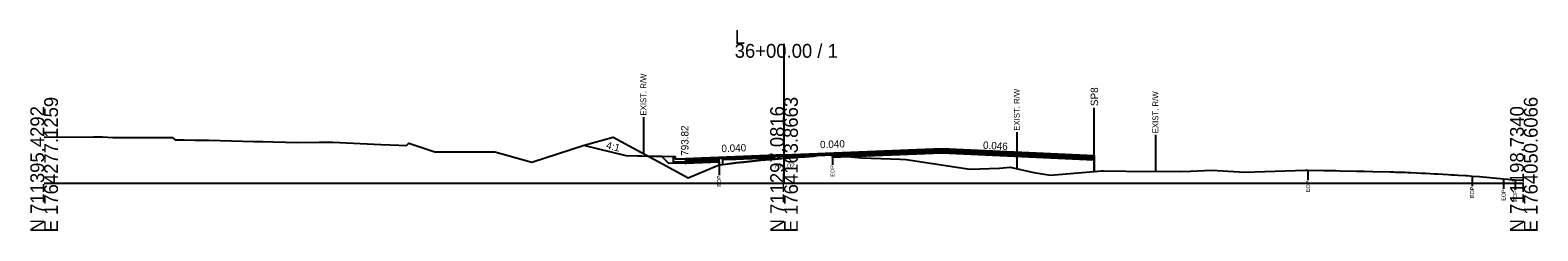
# Model space of a CAD drawing. Extents: x -26 to 5303, y -10 to 9578.
# Drawn here: x 1997.2 to 2302.8, y 5990.3 to 6031 of the extents above; entities that cross this region are included whole.
import ezdxf

# ---------------------------------------------------------------- set-up
doc = ezdxf.new("R2010")
doc.units = 0
for name, color, linetype in [('Default', 7, 'Continuous'), ('Exist CMT Pavement', 7, 'Continuous'), ('Exist Cross Section Cell', 7, 'Continuous'), ('Exist XS Ground Line', 7, 'Continuous'), ('Old_Level_10', 7, 'Continuous'), ('Old_Level_3', 7, 'Continuous'), ('Prop CMT Conc Surface', 7, 'Continuous'), ('Prop CMT Concrete Structures', 7, 'Continuous'), ('Prop CMT Pvmt Course 1', 7, 'Continuous'), ('Prop CMT Pvmt Course 2', 7, 'Continuous'), ('Prop CMT Pvmt Course 3', 7, 'Continuous'), ('Prop CMT Pvmt Surface', 7, 'Continuous'), ('Prop CMT Slope Grass', 7, 'Continuous'), ('Prop CMT Subgrade Earthwork', 7, 'Continuous'), ('Prop XS Earthwork Shape', 7, 'Continuous'), ('Prop XS Hydro Elevations', 7, 'Continuous'), ('Prop XS SE Text', 7, 'Continuous'), ('Prop XS Shear Point Element', 7, 'Continuous'), ('Prop XS Side Slope Text', 7, 'Continuous'), ('Prop XS Wedging', 7, 'Continuous')]:
    doc.layers.add(name, color=color, linetype=linetype)

msp = doc.modelspace()

# ---------------------------------------------------------------- linework, layer by layer
at = {"layer": 'Exist CMT Pavement'}
msp.add_lwpolyline([(2136.83, 6003.68), (2137.6, 6003.74), (2140.22, 6004.09), (2141.81, 6004.25), (2143.64, 6004.45), (2145.36, 6004.62), (2147.13, 6004.79), (2147.62, 6004.83), (2148.18, 6004.87), (2148.9, 6004.93), (2150.15, 6005.03), (2150.67, 6005.07), (2151.27, 6005.12), (2152.44, 6005.22), (2153.46, 6005.29), (2155.08, 6005.42), (2155.99, 6005.49), (2156.78, 6005.56), (2157.76, 6005.63), (2158.33, 6005.66), (2159.84, 6005.74)], dxfattribs=at)
at = {"layer": 'Exist Cross Section Cell'}
for p, q in [((2150, 6000), (2150, 6028.22)), ((2000, 6000), (2150, 6000)), ((2150, 6000), (2300, 6000))]:
    msp.add_line(p, q, dxfattribs=at)
at = {"layer": 'Exist XS Ground Line'}
msp.add_lwpolyline([(2000, 6009.34), (2009.97, 6009.41), (2011.8, 6009.37), (2013.9, 6009.25), (2015.51, 6009.25), (2017.23, 6009.26), (2017.86, 6009.23), (2019.12, 6009.27), (2019.49, 6009.27), (2021.39, 6009.26), (2022.36, 6009.26), (2023.41, 6009.26), (2025.46, 6009.26), (2025.98, 6009.26), (2026.55, 6008.76), (2028.4, 6008.74), (2030.52, 6008.71), (2032.08, 6008.69), (2033.43, 6008.67), (2042.53, 6008.42), (2044.33, 6008.4), (2046.4, 6008.34), (2051.42, 6008.23), (2055.77, 6008.3), (2058.5, 6008.28), (2068.25, 6007.85), (2071.93, 6007.67), (2073.43, 6007.59), (2073.93, 6008.09), (2074.72, 6007.83), (2079.2, 6006.32), (2086.39, 6006.31), (2091.35, 6006.31), (2093.8, 6005.63), (2098.9, 6004.27), (2109.51, 6007.67), (2115.35, 6009.3), (2124.51, 6004.37), (2130.55, 6001.04), (2136.05, 6003.38), (2136.83, 6003.68), (2137.6, 6003.74), (2139.83, 6004.05), (2140.22, 6004.09), (2141.81, 6004.25), (2143.64, 6004.45), (2145.36, 6004.62), (2147.13, 6004.79), (2147.82, 6004.84), (2148.18, 6004.87), (2148.9, 6004.93), (2150.15, 6005.03), (2150.67, 6005.07), (2151.27, 6005.12), (2152.44, 6005.22), (2153.46, 6005.29), (2154.22, 6005.35), (2155.08, 6005.42), (2155.99, 6005.49), (2156.78, 6005.56), (2157.76, 6005.63), (2158.33, 6005.66), (2159.84, 6005.74), (2161.45, 6005.5), (2165.71, 6005.14), (2173.52, 6004.84), (2174.78, 6004.78), (2187.67, 6002.82), (2193.72, 6003.02), (2195.83, 6003.2), (2200.66, 6002.17), (2204.02, 6001.58), (2213.61, 6002.39), (2214.32, 6002.46), (2214.72, 6002.47), (2219.38, 6002.43), (2230.4, 6002.35), (2232.43, 6002.41), (2235.27, 6002.53), (2236.72, 6002.62), (2237.88, 6002.54), (2243.36, 6002.23), (2255.72, 6002.6), (2256.23, 6002.61), (2259.42, 6002.58), (2260.55, 6002.56), (2261.85, 6002.53), (2262.73, 6002.51), (2266.04, 6002.44), (2267.63, 6002.4), (2269.38, 6002.32), (2272.93, 6002.28), (2273.58, 6002.26), (2273.97, 6002.24), (2275.97, 6002.18), (2276.49, 6002.16), (2277.1, 6002.13), (2278.27, 6002.07), (2279.28, 6002.03), (2280.04, 6001.99), (2280.91, 6001.94), (2281.81, 6001.89), (2282.59, 6001.85), (2283.58, 6001.79), (2284.72, 6001.73), (2285.36, 6001.69), (2285.9, 6001.67), (2286.69, 6001.62), (2288.17, 6001.52), (2288.49, 6001.51), (2289.51, 6001.4), (2290.99, 6001.35), (2295.9, 6000.86), (2296.77, 6000.78), (2297.11, 6000.74), (2298.21, 6000.69), (2300, 6000.61)], dxfattribs=at)
at = {"layer": 'Old_Level_10'}
for p, q in [((2121.49, 6013.39), (2121.49, 6005.99)), ((2197.2, 6010.31), (2197.2, 6002.91)), ((2225.3, 6009.79), (2225.3, 6002.39)), ((2136.83, 6003.68), (2136.83, 6001.63)), ((2159.84, 6005.74), (2159.84, 6003.69)), ((2256.23, 6002.61), (2256.23, 6000.56)), ((2289.51, 6001.4), (2289.51, 5999.35)), ((2295.9, 6000.86), (2295.9, 5998.81)), ((2298.21, 6000.69), (2298.21, 5998.64))]:
    msp.add_line(p, q, dxfattribs=at)
at = {"layer": 'Prop CMT Conc Surface'}
msp.add_line((2128, 6004.82), (2130, 6004.95), dxfattribs=at)
msp.add_lwpolyline([(2128, 6004.82), (2128, 6005.32), (2127.5, 6005.32)], dxfattribs=at)
at = {"layer": 'Prop CMT Concrete Structures'}
for points in [[(2130, 6004.95), (2128, 6004.82), (2128, 6005.32), (2127.5, 6005.32)], [(2127.5, 6005.32), (2127.5, 6004.3), (2130, 6004.37)]]:
    msp.add_lwpolyline(points, dxfattribs=at)
at = {"layer": 'Prop CMT Pvmt Course 1'}
for p, q in [((2182, 6007.03), (2212.9, 6005.6)), ((2212.9, 6005.35), (2182, 6006.78))]:
    msp.add_line(p, q, dxfattribs=at)
for points in [[(2150, 6005.75), (2182, 6007.03)], [(2182, 6006.78), (2159.84, 6005.9)], [(2150, 6005.75), (2130, 6004.95)], [(2130, 6004.7), (2136.83, 6004.98)], [(2130, 6004.95), (2130, 6004.7)], [(2130, 6004.75), (2130, 6004.5)], [(2136.83, 6004.98), (2150, 6005.5)], [(2136.83, 6004.98), (2136.83, 6004.98)], [(2159.84, 6005.9), (2150, 6005.5)], [(2150, 6005.5), (2150, 6005.75)], [(2150, 6005.5), (2150, 6005.5), (2150, 6005.5)], [(2159.84, 6005.9), (2159.84, 6005.9)]]:
    msp.add_lwpolyline(points, dxfattribs=at)
at = {"layer": 'Prop CMT Pvmt Course 2'}
for p, q in [((2182, 6006.78), (2212.9, 6005.35)), ((2212.9, 6005.02), (2182, 6006.45))]:
    msp.add_line(p, q, dxfattribs=at)
for points in [[(2159.84, 6005.9), (2182, 6006.78)], [(2136.83, 6004.98), (2130, 6004.7)], [(2130, 6004.7), (2130, 6004.37)], [(2130, 6004.37), (2136.83, 6004.64)], [(2130, 6004.5), (2130, 6004.17)], [(2136.83, 6004.64), (2136.83, 6004.98)], [(2182, 6006.45), (2159.84, 6005.56)], [(2159.84, 6005.56), (2159.84, 6005.9)]]:
    msp.add_lwpolyline(points, dxfattribs=at)
at = {"layer": 'Prop CMT Pvmt Course 3'}
for p, q in [((2182, 6006.45), (2212.9, 6005.02)), ((2212.9, 6004.69), (2182.01, 6006.11))]:
    msp.add_line(p, q, dxfattribs=at)
for points in [[(2136.83, 6004.64), (2130, 6004.37)], [(2130, 6004.37), (2130, 6004.04)], [(2130, 6004.04), (2136.83, 6004.31)], [(2130, 6004.17), (2130, 6003.84)], [(2136.83, 6004.31), (2136.83, 6004.64)], [(2159.84, 6005.56), (2182, 6006.45)], [(2182, 6006.12), (2159.84, 6005.23)], [(2159.84, 6005.23), (2159.84, 6005.56)]]:
    msp.add_lwpolyline(points, dxfattribs=at)
at = {"layer": 'Prop CMT Pvmt Surface'}
msp.add_line((2182, 6007.03), (2212.9, 6005.6), dxfattribs=at)
for points in [[(2150, 6005.75), (2182, 6007.03)], [(2150, 6005.75), (2130, 6004.95)]]:
    msp.add_lwpolyline(points, dxfattribs=at)
at = {"layer": 'Prop CMT Slope Grass'}
msp.add_line((2212.9, 6005.6), (2212.9, 6002.33), dxfattribs=at)
msp.add_lwpolyline([(2127.5, 6005.32), (2118, 6005.51), (2109.44, 6007.65)], dxfattribs=at)
at = {"layer": 'Prop CMT Subgrade Earthwork'}
for p, q in [((2136.83, 6004.31), (2136.83, 6003.68)), ((2159.84, 6005.23), (2159.84, 6005.74)), ((2182.01, 6006.11), (2212.9, 6004.69))]:
    msp.add_line(p, q, dxfattribs=at)
for points in [[(2130, 6004.04), (2126.66, 6003.94), (2125.24, 6005.36)], [(2136.83, 6004.31), (2130, 6004.04)], [(2159.84, 6005.23), (2182, 6006.12)]]:
    msp.add_lwpolyline(points, dxfattribs=at)
at = {"layer": 'Prop XS Earthwork Shape'}
for points in [[(2109.51, 6007.67), (2115.35, 6009.3), (2122.57, 6005.41), (2118, 6005.51), (2109.44, 6007.65)], [(2122.57, 6005.41), (2118, 6005.51), (2109.44, 6007.65), (2109.51, 6007.67), (2115.35, 6009.3)], [(2126.66, 6003.94), (2125.24, 6005.36), (2122.57, 6005.41), (2124.51, 6004.37), (2130.55, 6001.04), (2136.05, 6003.38), (2136.83, 6003.68), (2136.83, 6004.31), (2130, 6004.04)], [(2122.57, 6005.41), (2124.51, 6004.37), (2130.55, 6001.04), (2136.05, 6003.38), (2136.83, 6003.68), (2136.83, 6004.31), (2130, 6004.04), (2126.66, 6003.94), (2125.24, 6005.36)], [(2159.84, 6005.23), (2159.84, 6005.74), (2161.45, 6005.5), (2163.09, 6005.36)], [(2163.09, 6005.36), (2165.71, 6005.14), (2173.52, 6004.84), (2174.78, 6004.78), (2187.67, 6002.82), (2193.72, 6003.02), (2195.83, 6003.2), (2200.66, 6002.17), (2204.02, 6001.58), (2212.9, 6002.33), (2212.9, 6004.69), (2182, 6006.12)]]:
    msp.add_lwpolyline(points, close=True, dxfattribs=at)
at = {"layer": 'Prop XS Shear Point Element'}
msp.add_line((2212.9, 6005.6), (2212.9, 6015.28), dxfattribs=at)
at = {"layer": 'Prop XS Wedging'}
for points in [[(2137.6, 6003.73), (2137.6, 6005.13), (2140.22, 6005.21), (2141.81, 6005.26), (2143.64, 6005.31), (2145.36, 6005.36), (2147.13, 6005.42), (2147.62, 6005.43), (2148.18, 6005.45), (2148.9, 6005.47), (2150, 6005.5), (2150.15, 6005.51), (2150.67, 6005.52), (2151.27, 6005.54), (2152.44, 6005.58), (2153.46, 6005.61), (2155.08, 6005.66), (2155.99, 6005.68), (2156.78, 6005.71), (2157.76, 6005.74), (2158.33, 6005.75), (2159.84, 6005.8), (2159.84, 6005.74), (2158.33, 6005.66), (2157.76, 6005.63), (2156.78, 6005.56), (2155.99, 6005.49), (2155.08, 6005.42), (2153.46, 6005.3), (2152.44, 6005.22), (2151.27, 6005.12), (2150.67, 6005.07), (2150.15, 6005.03), (2150, 6005.02), (2148.9, 6004.93), (2148.18, 6004.87), (2147.62, 6004.83), (2147.13, 6004.79), (2145.36, 6004.62), (2143.64, 6004.45), (2141.81, 6004.25), (2140.22, 6004.09)], [(2137.6, 6003.73), (2137.6, 6005.13), (2140.22, 6005.21), (2141.81, 6005.26), (2143.64, 6005.31), (2145.36, 6005.36), (2147.13, 6005.42), (2147.62, 6005.43), (2148.18, 6005.45), (2148.9, 6005.47), (2150, 6005.5), (2150.15, 6005.51), (2150.67, 6005.52), (2151.27, 6005.54), (2152.44, 6005.58), (2153.46, 6005.61), (2155.08, 6005.66), (2155.58, 6005.67), (2155.77, 6005.48), (2155.08, 6005.42), (2153.46, 6005.3), (2152.44, 6005.22), (2151.27, 6005.12), (2150.67, 6005.07), (2150.15, 6005.03), (2150, 6005.02), (2148.9, 6004.93), (2148.18, 6004.87), (2147.62, 6004.83), (2147.13, 6004.79), (2145.36, 6004.62), (2143.64, 6004.45), (2141.81, 6004.25), (2140.22, 6004.09)], [(2137.6, 6003.73), (2137.6, 6004.8), (2140.22, 6004.88), (2141.81, 6004.93), (2143.64, 6004.98), (2145.36, 6005.03), (2147.13, 6005.09), (2147.62, 6005.1), (2148.09, 6005.12), (2148.32, 6004.88), (2147.62, 6004.83), (2147.13, 6004.79), (2145.36, 6004.62), (2143.64, 6004.45), (2141.81, 6004.25), (2140.22, 6004.09)]]:
    msp.add_lwpolyline(points, close=True, dxfattribs=at)

# ---------------------------------------------------------------- texts
at = {"layer": 'Default'}
msp.add_text('-', height=0.0001, dxfattribs=at).set_placement((2000, 6000))
at = {"layer": 'Exist Cross Section Cell'}
for s, p in [('36+00.00 / 1', (2140, 6025.42)), ('L', (2140, 6028.22))]:
    msp.add_text(s, height=2.8, dxfattribs=at).set_placement(p)
for s, p in [('E 1764277.1259', (2002.8, 5990)), ('E 1764163.8663', (2152.8, 5990)), ('E 1764050.6066', (2302.8, 5990)), ('N 711395.4292', (2000, 5990)), ('N 711297.0816', (2150, 5990)), ('N 711198.7340', (2300, 5990))]:
    msp.add_text(s, height=2.8, rotation=90, dxfattribs=at).set_placement(p)
at = {"layer": 'Old_Level_10'}
for s, height, p in [('EXIST. R/W', 1.181, (2122.08, 6013.7)), ('EXIST. R/W', 1.181, (2197.79, 6010.61)), ('EXIST. R/W', 1.181, (2225.89, 6010.09)), ('EOP', 0.787, (2137.22, 5999.23)), ('EOP', 0.787, (2160.23, 6001.3)), ('EOP', 0.787, (2256.63, 5998.17)), ('EOP', 0.787, (2289.9, 5996.96)), ('EOP', 0.787, (2296.29, 5996.41)), ('EOP', 0.787, (2298.61, 5996.24))]:
    msp.add_text(s, height=height, rotation=90, dxfattribs=at).set_placement(p)
at = {"layer": 'Old_Level_3'}
msp.add_text('794.02', height=1, dxfattribs=at).set_placement((2147.96, 6003.02))
at = {"layer": 'Prop XS Hydro Elevations'}
msp.add_text('793.82', height=1.5, rotation=90, dxfattribs=at).set_placement((2130.63, 6005.54))
at = {"layer": 'Prop XS SE Text'}
for s, rotation, p in [('0.040', 2.2906, (2137.34, 6006.25)), ('0.040', 2.2906, (2157.34, 6007.05)), ('0.046', 356.903, (2190.32, 6006.96))]:
    msp.add_text(s, height=1.5, rotation=rotation, dxfattribs=at).set_placement(p)
at = {"layer": 'Prop XS Shear Point Element'}
msp.add_text('SP8', height=1.5, rotation=90, dxfattribs=at).set_placement((2213.68, 6015.62))
at = {"layer": 'Prop XS Side Slope Text'}
msp.add_text('4:1', height=1.5, rotation=345.9638, dxfattribs=at).set_placement((2113.83, 6007.03))

doc.saveas('drawing.dxf')
